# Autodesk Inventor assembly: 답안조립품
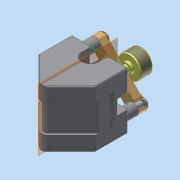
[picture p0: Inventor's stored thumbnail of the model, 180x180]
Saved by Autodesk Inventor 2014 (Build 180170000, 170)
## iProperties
Created: 2025-02
Part Number: 답안조립품
Document SubType Name: Assembly
Designer: dg
Author: dg
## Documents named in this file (9)
- C:\Users\dg\Desktop\750203V1007\답안조립품.iam
- C:\Users\dg\Desktop\750203V1007\본체.ipt
- C:\Users\dg\Documents\Inventor\조.ipt
- C:\Users\dg\Desktop\750203V1007\가져온 구성요소\가공품\가공품.ipt
- C:\Users\dg\Desktop\750203V1007\가져온 구성요소\고정핀\고정핀.ipt
- C:\Users\dg\Desktop\750203V1007\가져온 구성요소\노브\노브.ipt
- C:\Users\dg\Desktop\750203V1007\가져온 구성요소\드릴부시\드릴부시.ipt
- C:\Users\dg\Desktop\750203V1007\가져온 구성요소\서포터\서포터.ipt
- C:\Users\dg\Desktop\750203V1007\가져온 구성요소\스트리퍼 볼트 M6x10\스트리퍼 볼트 M6x10.ipt
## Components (2 placed, 2 different names)
1. 가공품:1 — 플러쉬:1
2. 고정핀:1
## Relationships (1: Flush 1)
- 플러쉬:1 [Flush]: 가공품:1
